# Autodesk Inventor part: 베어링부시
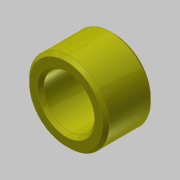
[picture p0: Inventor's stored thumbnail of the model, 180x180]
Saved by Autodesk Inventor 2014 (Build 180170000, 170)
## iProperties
Created: 2019-03
Part Number: 베어링부시
Material: 강철, 연강
Document SubType Name: Modeling
Designer: mduedu
Density: 1 g/cm^3
Appearance: 노란색
Author: mduedu
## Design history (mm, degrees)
sketch "스케치1"
  geometry: L1 (-7.5, 12.5)-(7.5, 12.5); L2 (7.5, 12.5)-(7.5, 8); L3 (7.5, 8)-(-7.5, 8); L4 (-7.5, 8)-(-7.5, 12.5); L5 (-7.5, 0)-(7.5, 0); 3 further points
  constraints: 10 end point, 2 midpoint, 2 parallel, 2 perpendicular, 2 vertical alignment, 1 coincident, 1 horizontal
  dimensions: "d0" = 16 diameter of L3 L5; "d2" = 25 diameter of L1 L5; "d3" = 15 distance of L1.start L1.end
revolve "회전1" sketch "스케치1" stored, may be unused: angle "d4" = 90 deg
chamfer "모따기1" distance "d5" = 1; stored, may be unused: second distance "d6" = 2, angle "d7" = 45 deg
chamfer "모따기2" distance "d8" = 1; stored, may be unused: second distance "d9" = 2, angle "d10" = 45 deg
node "솔리드1"
